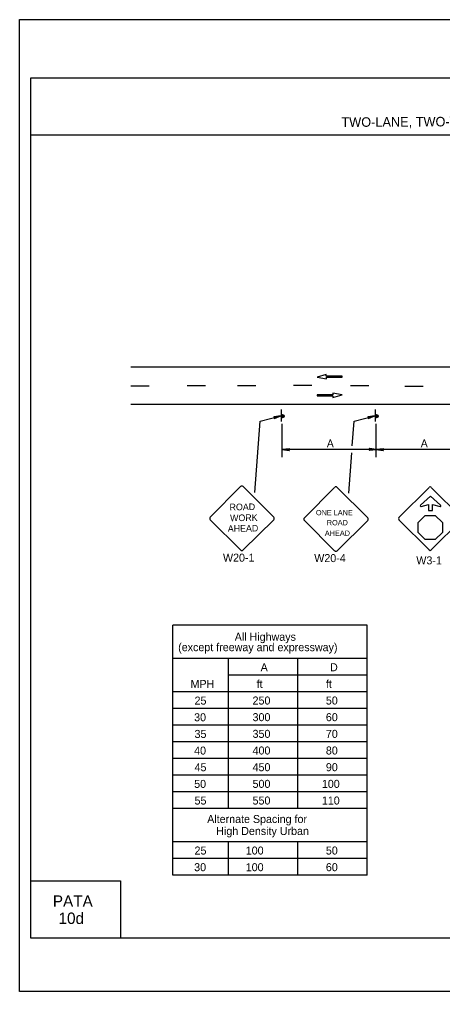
# Model space of a CAD drawing. Extents: x -14145 to -13662, y 30244 to 30661.
# Drawn here: x -13824.17 to -13813.07, y 30505.81 to 30531.31 of the extents above; entities that cross this region are included whole.
import ezdxf

# ---------------------------------------------------------------- set-up
doc = ezdxf.new("R2010")
doc.units = 0
for name, color, linetype in [('1', 7, 'Continuous'), ('10', 7, 'Continuous'), ('2', 7, 'Continuous'), ('3', 7, 'Continuous'), ('4', 7, 'Continuous'), ('61', 7, 'Continuous')]:
    doc.layers.add(name, color=color, linetype=linetype)

msp = doc.modelspace()

# ---------------------------------------------------------------- linework, layer by layer
at = {"layer": '1'}
for p, q in [((-13821.248, 30522.196), (-13794.968, 30522.196)), ((-13816.119, 30521.993), (-13816.36, 30521.927)), ((-13816.119, 30521.948), (-13816.119, 30521.993)), ((-13816.36, 30521.927), (-13816.117, 30521.881)), ((-13815.703, 30521.948), (-13816.119, 30521.948)), ((-13816.117, 30521.881), (-13816.117, 30521.926)), ((-13816.117, 30521.926), (-13815.703, 30521.926)), ((-13815.703, 30521.926), (-13815.703, 30521.948)), ((-13820.768, 30521.686), (-13821.248, 30521.686)), ((-13819.292, 30521.698), (-13819.772, 30521.698)), ((-13817.972, 30521.692), (-13818.452, 30521.692)), ((-13816.496, 30521.704), (-13816.976, 30521.704)), ((-13815.703, 30521.457), (-13815.947, 30521.503)), ((-13815.947, 30521.503), (-13815.947, 30521.458)), ((-13815.002, 30521.692), (-13815.482, 30521.692)), ((-13813.574, 30521.68), (-13814.054, 30521.68)), ((-13821.248, 30521.212), (-13794.968, 30521.212)), ((-13815.947, 30521.458), (-13816.36, 30521.458)), ((-13816.36, 30521.458), (-13816.36, 30521.436)), ((-13816.36, 30521.436), (-13815.944, 30521.436)), ((-13815.944, 30521.391), (-13815.703, 30521.457)), ((-13815.944, 30521.436), (-13815.944, 30521.391)), ((-13817.303, 30521.073), (-13817.303, 30520.761)), ((-13817.303, 30521.073), (-13817.303, 30520.761)), ((-13814.837, 30521.073), (-13814.837, 30520.761)), ((-13814.837, 30521.073), (-13814.837, 30520.761)), ((-13817.993, 30518.896), (-13817.856, 30520.766)), ((-13817.856, 30520.766), (-13817.309, 30520.906)), ((-13817.273, 30519.824), (-13817.273, 30520.698)), ((-13815.437, 30520.123), (-13815.39, 30520.766)), ((-13815.39, 30520.766), (-13814.843, 30520.906)), ((-13814.807, 30519.824), (-13814.807, 30520.698)), ((-13814.807, 30520.028), (-13817.273, 30520.028)), ((-13815.528, 30518.883), (-13815.451, 30519.937)), ((-13812.341, 30520.028), (-13814.807, 30520.028)), ((-13818.369, 30519.054), (-13819.164, 30518.251)), ((-13817.5, 30518.251), (-13818.303, 30519.054)), ((-13815.899, 30519.033), (-13816.694, 30518.23)), ((-13815.03, 30518.23), (-13815.833, 30519.033)), ((-13814.215, 30518.239), (-13813.419, 30519.033)), ((-13813.367, 30519.033), (-13812.571, 30518.239)), ((-13813.382, 30518.802), (-13813.646, 30518.562)), ((-13813.118, 30518.562), (-13813.382, 30518.802)), ((-13813.63, 30518.532), (-13813.437, 30518.583)), ((-13813.437, 30518.583), (-13813.437, 30518.424)), ((-13813.437, 30518.424), (-13813.327, 30518.424)), ((-13813.327, 30518.424), (-13813.327, 30518.583)), ((-13813.327, 30518.583), (-13813.134, 30518.532)), ((-13819.164, 30518.185), (-13818.369, 30517.39)), ((-13818.303, 30517.39), (-13817.5, 30518.185)), ((-13816.694, 30518.164), (-13815.899, 30517.369)), ((-13815.833, 30517.369), (-13815.03, 30518.164)), ((-13813.419, 30517.39), (-13814.215, 30518.185)), ((-13812.571, 30518.185), (-13813.367, 30517.39)), ((-13820.144, 30508.86), (-13820.144, 30515.416)), ((-13815.045, 30515.416), (-13820.144, 30515.416)), ((-13815.045, 30508.86), (-13815.045, 30515.416)), ((-13815.045, 30514.542), (-13820.145, 30514.542)), ((-13818.687, 30510.608), (-13818.687, 30514.542)), ((-13816.867, 30510.608), (-13816.867, 30514.542)), ((-13815.045, 30514.105), (-13818.687, 30514.105)), ((-13815.045, 30513.668), (-13820.145, 30513.668)), ((-13815.045, 30513.231), (-13820.145, 30513.231)), ((-13815.045, 30512.794), (-13820.145, 30512.794)), ((-13815.045, 30512.357), (-13820.145, 30512.357)), ((-13815.045, 30511.92), (-13820.145, 30511.92)), ((-13815.045, 30511.482), (-13820.145, 30511.482)), ((-13815.045, 30511.045), (-13820.145, 30511.045)), ((-13815.045, 30510.608), (-13820.145, 30510.608)), ((-13815.045, 30509.734), (-13820.145, 30509.734)), ((-13818.687, 30508.86), (-13818.687, 30509.734)), ((-13816.867, 30508.86), (-13816.867, 30509.734)), ((-13815.045, 30509.297), (-13820.145, 30509.297)), ((-13815.045, 30508.86), (-13820.144, 30508.86))]:
    msp.add_line(p, q, dxfattribs=at)
for points in [[(-13817.489, 30520.882), (-13817.477, 30520.87), (-13817.309, 30520.906), (-13817.489, 30520.882), (-13817.495, 30520.888), (-13817.309, 30520.906), (-13817.471, 30520.852), (-13817.477, 30520.84), (-13817.309, 30520.906), (-13817.483, 30520.828), (-13817.477, 30520.84)], [(-13815.023, 30520.882), (-13815.011, 30520.87), (-13814.843, 30520.906), (-13815.023, 30520.882), (-13815.029, 30520.888), (-13814.843, 30520.906), (-13815.005, 30520.852), (-13815.011, 30520.84), (-13814.843, 30520.906), (-13815.017, 30520.828), (-13815.011, 30520.84)], [(-13817.093, 30519.998), (-13817.099, 30520.01), (-13817.273, 30520.022), (-13817.093, 30519.998), (-13817.087, 30519.992), (-13817.273, 30520.022), (-13817.099, 30520.028), (-13817.093, 30520.04), (-13817.273, 30520.022), (-13817.087, 30520.052), (-13817.093, 30520.04)], [(-13814.987, 30520.052), (-13814.981, 30520.034), (-13814.807, 30520.028), (-13814.987, 30520.052), (-13814.993, 30520.058), (-13814.807, 30520.028), (-13814.981, 30520.022), (-13814.987, 30520.004), (-13814.807, 30520.028), (-13814.993, 30519.998), (-13814.987, 30520.004)], [(-13814.627, 30519.998), (-13814.633, 30520.01), (-13814.807, 30520.022), (-13814.627, 30519.998), (-13814.621, 30519.992), (-13814.807, 30520.022), (-13814.633, 30520.028), (-13814.627, 30520.04), (-13814.807, 30520.022), (-13814.621, 30520.052), (-13814.627, 30520.04)], [(-13813.52, 30517.664), (-13813.705, 30517.85), (-13813.705, 30518.112), (-13813.52, 30518.298), (-13813.257, 30518.298), (-13813.071, 30518.112), (-13813.071, 30517.85), (-13813.257, 30517.664), (-13813.52, 30517.664)]]:
    msp.add_lwpolyline(points, dxfattribs=at)
for centre in [(-13817.264, 30520.9), (-13814.798, 30520.9)]:
    msp.add_circle(centre, 0.0408, dxfattribs=at)
for centre, radius, start, end in [((-13817.269, 30520.908), 0.0214, 189.521, 184.2501), ((-13814.803, 30520.908), 0.0214, 189.521, 184.2501), ((-13818.336, 30519.021), 0.0465, 45, 135), ((-13815.866, 30519), 0.0465, 45, 135), ((-13813.393, 30519.007), 0.0376, 45, 135), ((-13813.634, 30518.549), 0.0178, 132.5836, 284.3022), ((-13813.129, 30518.549), 0.0178, 255.6978, 47.4164), ((-13819.131, 30518.218), 0.0465, 135, 225), ((-13817.533, 30518.218), 0.0465, 315, 45), ((-13816.661, 30518.197), 0.0465, 135, 225), ((-13815.063, 30518.197), 0.0465, 315, 45), ((-13814.188, 30518.212), 0.0376, 135, 225), ((-13818.336, 30517.423), 0.0465, 225, 315), ((-13813.393, 30517.417), 0.0376, 225, 315), ((-13815.866, 30517.402), 0.0465, 225, 315)]:
    msp.add_arc(centre, radius, start, end, dxfattribs=at)
at = {"layer": '10'}
for p, q in [((-13823.874, 30529.777), (-13792.422, 30529.777)), ((-13823.874, 30507.207), (-13823.874, 30529.777)), ((-13823.874, 30528.277), (-13792.422, 30528.277)), ((-13823.874, 30508.707), (-13821.524, 30508.707)), ((-13821.524, 30508.707), (-13821.524, 30507.207)), ((-13792.422, 30507.207), (-13823.874, 30507.207))]:
    msp.add_line(p, q, dxfattribs=at)
at = {"layer": '61'}
msp.add_lwpolyline([(-13824.174, 30531.307), (-13791.174, 30531.307), (-13791.174, 30505.807), (-13824.174, 30505.807)], close=True, dxfattribs=at)

# ---------------------------------------------------------------- texts
at = {"layer": '1'}
for s, height, rotation, p in [('ROAD', 0.1735, 0.7566, (-13818.656, 30518.429)), ('WORK', 0.1733, 0.7588, (-13818.643, 30518.144)), ('AHEAD', 0.1735, 0.7481, (-13818.703, 30517.866))]:
    msp.add_text(s, height=height, rotation=rotation, dxfattribs=at).set_placement(p)
for s, height, p in [('ONE LANE', 0.1386, (-13816.391, 30518.301)), ('ROAD', 0.1389, (-13816.106, 30518.038)), ('AHEAD', 0.139, (-13816.158, 30517.761))]:
    msp.add_text(s, height=height, dxfattribs=at).set_placement(p)
at = {"layer": '2'}
for s, p in [('A', (-13816.107, 30520.079)), ('A', (-13813.641, 30520.079)), ('W20-1', (-13818.831, 30517.083)), ('W20-4', (-13816.435, 30517.072)), ('W3-1', (-13813.756, 30517.012)), ('A', (-13817.842, 30514.209)), ('D', (-13816.021, 30514.209)), ('MPH', (-13819.682, 30513.771)), ('ft', (-13817.947, 30513.771)), ('ft', (-13816.128, 30513.771)), ('25', (-13819.577, 30513.334)), ('250', (-13818.054, 30513.336)), ('50', (-13816.13, 30513.336)), ('30', (-13819.588, 30512.897)), ('300', (-13818.054, 30512.899)), ('60', (-13816.13, 30512.899)), ('35', (-13819.577, 30512.46)), ('350', (-13818.054, 30512.462)), ('70', (-13816.13, 30512.462)), ('40', (-13819.588, 30512.023)), ('400', (-13818.054, 30512.025)), ('80', (-13816.13, 30512.025)), ('45', (-13819.577, 30511.586)), ('450', (-13818.054, 30511.587)), ('90', (-13816.13, 30511.587)), ('50', (-13819.587, 30511.149)), ('500', (-13818.054, 30511.15)), ('100', (-13816.235, 30511.15)), ('55', (-13819.577, 30510.712)), ('550', (-13818.054, 30510.713)), ('110', (-13816.235, 30510.713)), ('25', (-13819.577, 30509.401)), ('100', (-13818.233, 30509.401)), ('50', (-13816.13, 30509.401)), ('30', (-13819.587, 30508.964)), ('100', (-13818.233, 30508.964)), ('60', (-13816.13, 30508.964))]:
    msp.add_text(s, height=0.21, dxfattribs=at).set_placement(p)
at = {"layer": '3'}
for s, height, p in [('All Highways', 0.20979, (-13818.522, 30515.008)), ('(except freeway and expressway)', 0.21, (-13820.007, 30514.735)), ('Alternate Spacing for', 0.20979, (-13819.245, 30510.228)), ('High Density Urban', 0.20979, (-13819.007, 30509.914))]:
    msp.add_text(s, height=height, dxfattribs=at).set_placement(p)
at = {"layer": '4'}
msp.add_text('TWO-LANE, TWO-WAY ROADWAY - STOP SIGN-CONTROLLED LANE CLOSURE', height=0.25, rotation=0.31, dxfattribs=at).set_placement((-13815.721, 30528.487))
for s, p in [('PATA', (-13823.296, 30508.03)), ('10d', (-13823.147, 30507.58))]:
    msp.add_text(s, height=0.3, dxfattribs=at).set_placement(p)

doc.saveas('drawing.dxf')
